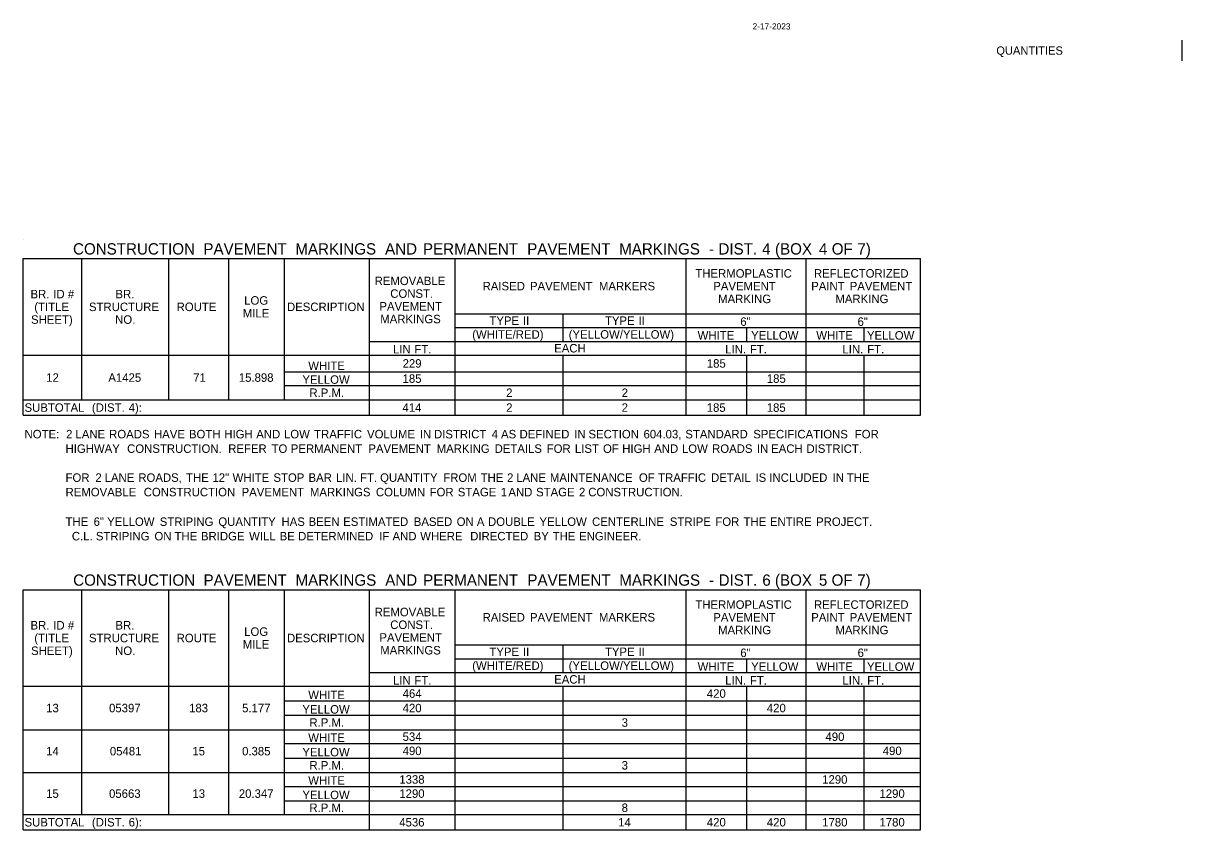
# Model space of a CAD drawing. Extents: x 544255 to 1930787, y -1947044 to 596640.
# Drawn here: x 544975 to 545794, y -1946596 to -1946026 of the extents above; entities that cross this region are included whole.
import ezdxf

# ---------------------------------------------------------------- set-up
doc = ezdxf.new("R2010")
doc.units = 0
doc.layers.add('Default', color=7, linetype='Continuous')
doc.layers.add('R_Border Prem', color=7, linetype='Continuous')

msp = doc.modelspace()

# ---------------------------------------------------------------- linework, layer by layer
at = {"layer": 'Default'}
for p, q in [((545794.28, -1946038.1), (545794.28, -1946052.8)), ((544975.46, -1946178.75), (544975.46, -1946178.75)), ((544975.46, -1946192.4), (545609.7, -1946192.4)), ((544975.46, -1946192.4), (545280.64, -1946192.4)), ((544975.46, -1946303.06), (544975.46, -1946192.4)), ((545016.9, -1946292.34), (545016.9, -1946192.4)), ((545078.33, -1946292.34), (545078.33, -1946192.4)), ((545120.74, -1946292.34), (545120.74, -1946192.4)), ((545160.23, -1946292.34), (545160.23, -1946192.4)), ((545220.19, -1946303.06), (545220.19, -1946192.4)), ((545280.64, -1946303.06), (545280.64, -1946192.4)), ((545443.95, -1946303.06), (545443.95, -1946192.4)), ((545528.78, -1946260.65), (545528.78, -1946192.4)), ((545528.78, -1946303.06), (545528.78, -1946192.4)), ((545609.7, -1946303.06), (545609.7, -1946192.4)), ((545280.64, -1946231.4), (545609.7, -1946231.4)), ((545357.18, -1946250.9), (545357.18, -1946231.4)), ((545280.64, -1946241.15), (545609.7, -1946241.15)), ((545486.85, -1946250.9), (545486.85, -1946241.15)), ((545569.73, -1946250.9), (545569.73, -1946241.15)), ((545220.19, -1946250.9), (545609.7, -1946250.9)), ((545220.19, -1946260.65), (545220.19, -1946250.9)), ((544975.46, -1946260.65), (545160.23, -1946260.65)), ((544975.46, -1946260.65), (545120.74, -1946260.65)), ((545120.74, -1946260.65), (545609.7, -1946260.65)), ((545357.18, -1946303.06), (545357.18, -1946260.65)), ((545443.95, -1946260.65), (545528.78, -1946260.65)), ((545486.85, -1946303.06), (545486.85, -1946260.65)), ((545528.78, -1946260.65), (545609.7, -1946260.65)), ((545569.73, -1946303.06), (545569.73, -1946260.65)), ((545160.23, -1946272.35), (545609.7, -1946272.35)), ((545160.23, -1946282.1), (545609.7, -1946282.1)), ((544975.46, -1946292.34), (545609.7, -1946292.34)), ((545220.19, -1946303.06), (545220.19, -1946292.34)), ((544975.46, -1946303.06), (545609.7, -1946303.06)), ((544975.46, -1946426.4), (545609.7, -1946426.4)), ((544975.46, -1946426.4), (545280.64, -1946426.4)), ((544975.46, -1946596.05), (544975.46, -1946426.4)), ((545016.9, -1946585.32), (545016.9, -1946426.4)), ((545078.33, -1946585.32), (545078.33, -1946426.4)), ((545120.74, -1946585.32), (545120.74, -1946426.4)), ((545160.23, -1946585.32), (545160.23, -1946426.4)), ((545220.19, -1946596.05), (545220.19, -1946426.4)), ((545280.64, -1946596.05), (545280.64, -1946426.4)), ((545443.95, -1946596.05), (545443.95, -1946426.4)), ((545528.78, -1946494.65), (545528.78, -1946426.4)), ((545528.78, -1946596.05), (545528.78, -1946426.4)), ((545609.7, -1946596.05), (545609.7, -1946426.4)), ((545280.64, -1946465.4), (545609.7, -1946465.4)), ((545357.18, -1946484.9), (545357.18, -1946465.4)), ((545280.64, -1946475.15), (545609.7, -1946475.15)), ((545486.85, -1946484.9), (545486.85, -1946475.15)), ((545569.73, -1946484.9), (545569.73, -1946475.15)), ((545220.19, -1946484.9), (545609.7, -1946484.9)), ((545220.19, -1946494.65), (545220.19, -1946484.9)), ((544975.46, -1946494.65), (545160.23, -1946494.65)), ((544975.46, -1946494.65), (545120.74, -1946494.65)), ((545120.74, -1946494.65), (545609.7, -1946494.65)), ((545357.18, -1946596.05), (545357.18, -1946494.65)), ((545443.95, -1946494.65), (545528.78, -1946494.65)), ((545486.85, -1946596.05), (545486.85, -1946494.65)), ((545528.78, -1946494.65), (545609.7, -1946494.65)), ((545569.73, -1946596.05), (545569.73, -1946494.65)), ((545160.23, -1946504.89), (545609.7, -1946504.89)), ((545160.23, -1946515.12), (545609.7, -1946515.12)), ((544975.46, -1946525.36), (545609.7, -1946525.36)), ((545160.23, -1946535.11), (545609.7, -1946535.11)), ((545160.23, -1946545.35), (545609.7, -1946545.35)), ((544975.46, -1946555.59), (545609.7, -1946555.59)), ((545160.23, -1946565.34), (545609.7, -1946565.34)), ((545160.23, -1946575.57), (545609.7, -1946575.57)), ((544975.46, -1946585.32), (545609.7, -1946585.32)), ((545220.19, -1946596.05), (545220.19, -1946585.32)), ((544975.46, -1946596.05), (545609.7, -1946596.05))]:
    msp.add_line(p, q, dxfattribs=at)

# ---------------------------------------------------------------- texts
for s, height, p in [('CONSTRUCTION', 8, (545010.7, -1946189.57)), (' PAVEMENT', 8, (545099.85, -1946189.57)), (' MARKINGS', 8, (545164.84, -1946189.57)), (' AND', 8, (545228.25, -1946189.57)), (' PERMANENT', 8, (545255.02, -1946189.57)), (' PAVEMENT', 8, (545328.7, -1946189.57)), (' MARKINGS', 8, (545393.68, -1946189.57)), (' -', 8, (545457.1, -1946189.57)), (' DIST.', 8, (545463.84, -1946189.57)), (' 4', 8, (545494.74, -1946189.57)), (' (BOX', 8, (545503.81, -1946189.57)), (' 4', 8, (545534.84, -1946189.57)), (' OF', 8, (545543.9, -1946189.57)), (' 7)', 8, (545562.01, -1946189.57)), ('THERMOPLASTIC', 6, (545450.48, -1946205.9)), ('REFLECTORIZED', 6, (545534.28, -1946205.9)), ('REMOVABLE', 6, (545223.84, -1946211.15)), ('RAISED', 6, (545300.14, -1946214.9)), (' PAVEMENT', 6, (545331.4, -1946214.9)), (' MARKERS', 6, (545380.14, -1946214.9)), ('PAVEMENT', 6, (545463.16, -1946214.9)), ('PAINT', 6, (545532.38, -1946214.9)), (' PAVEMENT', 6, (545557.36, -1946214.9)), ('BR.', 6, (544980.66, -1946220.52)), (' ID', 6, (544994.52, -1946220.52)), (' #', 6, (545004.81, -1946220.52)), ('BR.', 6, (545040.68, -1946220.52)), ('LOG', 6, (545131.65, -1946225.02)), ('CONST.', 6, (545234.87, -1946220.15)), ('MARKING', 6, (545466.59, -1946223.9)), ('MARKING', 6, (545549.47, -1946223.9)), ('(TITLE', 6, (544983.35, -1946229.52)), ('STRUCTURE', 6, (545021.97, -1946229.52)), ('ROUTE', 6, (545083.9, -1946229.52)), ('MILE', 6, (545130.68, -1946234.02)), ('DESCRIPTION', 6, (545161.9, -1946229.52)), ('PAVEMENT', 6, (545227.21, -1946229.15)), ('SHEET)', 6, (544981.03, -1946238.52)), ('NO.', 6, (545040.45, -1946238.52)), ('MARKINGS', 6, (545227.8, -1946238.15)), ('TYPE', 6, (545304.95, -1946239.27)), (' II', 6, (545326.43, -1946239.27)), ('TYPE', 6, (545386.6, -1946239.27)), (' II', 6, (545408.09, -1946239.27)), ('6"', 6, (545482.26, -1946239.95)), ('6"', 6, (545565.13, -1946239.95)), ('(WHITE/RED)', 6, (545292.82, -1946249.02)), ('(YELLOW/YELLOW)', 6, (545360.97, -1946249.02)), ('WHITE', 6, (545452.11, -1946249.7)), ('YELLOW', 6, (545489.89, -1946249.7)), ('WHITE', 6, (545535.96, -1946249.7)), ('YELLOW', 6, (545571.79, -1946249.7)), ('EACH', 6, (545350.74, -1946258.77)), ('LIN', 6, (545236.84, -1946259.45)), (' FT.', 6, (545249.67, -1946259.45)), ('LIN.', 6, (545471.57, -1946259.45)), (' FT.', 6, (545486.83, -1946259.45)), ('LIN.', 6, (545554.45, -1946259.45)), (' FT.', 6, (545569.71, -1946259.45)), ('WHITE', 6, (545176.93, -1946271.15)), ('229', 6, (545243.61, -1946269.5)), ('185', 6, (545458.58, -1946269.5)), ('12', 6, (544991.74, -1946279.49)), ('A1425', 6, (545035.66, -1946279.49)), ('71', 6, (545095.64, -1946279.49)), ('15.898', 6, (545127.85, -1946279.49)), ('YELLOW', 6, (545172.79, -1946280.9)), ('185', 6, (545243.59, -1946280.22)), ('185', 6, (545500.99, -1946280.22)), ('R.P.M.', 6, (545177.77, -1946290.22)), ('2', 6, (545316.8, -1946290.22)), ('2', 6, (545398.46, -1946290.22)), ('SUBTOTAL', 6, (544976.44, -1946300.7)), (' (DIST.', 6, (545021.83, -1946300.7)), (' 4):', 6, (545047.8, -1946300.7)), ('414', 6, (545243.52, -1946300.7)), ('2', 6, (545316.79, -1946300.7)), ('2', 6, (545398.44, -1946300.7)), ('185', 6, (545458.54, -1946300.7)), ('185', 6, (545500.95, -1946300.7)), ('NOTE:', 6, (544976.44, -1946319.47)), ('  2', 6, (545001.33, -1946319.47)), (' LANE', 6, (545010.2, -1946319.47)), (' ROADS', 6, (545033.98, -1946319.47)), (' HAVE', 6, (545065.68, -1946319.47)), (' BOTH', 6, (545090.4, -1946319.47)), (' HIGH', 6, (545115.34, -1946319.47)), (' AND', 6, (545137.95, -1946319.47)), (' LOW', 6, (545157.53, -1946319.47)), (' TRAFFIC', 6, (545178.86, -1946319.47)), (' VOLUME', 6, (545216.25, -1946319.47)), (' IN', 6, (545253.53, -1946319.47)), (' DISTRICT', 6, (545263.56, -1946319.47)), (' 4', 6, (545304.37, -1946319.47)), (' AS', 6, (545310.95, -1946319.47)), (' DEFINED', 6, (545324.03, -1946319.47)), (' IN', 6, (545362.71, -1946319.47)), (' SECTION', 6, (545372.73, -1946319.47)), (' 604.03,', 6, (545411.64, -1946319.47)), (' STANDARD', 6, (545441.18, -1946319.47)), (' SPECIFICATIONS', 6, (545489.18, -1946319.47)), (' FOR', 6, (545560.95, -1946319.47)), ('             HIGHWAY', 6, (544976.44, -1946329.7)), (' CONSTRUCTION.', 6, (545046.69, -1946329.7)), (' REFER', 6, (545118.15, -1946329.7)), (' TO', 6, (545148.78, -1946329.7)), (' PERMANENT', 6, (545162.38, -1946329.7)), (' PAVEMENT', 6, (545217.18, -1946329.7)), (' MARKING', 6, (545265.46, -1946329.7)), (' DETAILS', 6, (545306.39, -1946329.7)), (' FOR', 6, (545343.23, -1946329.7)), (' LIST', 6, (545363.14, -1946329.7)), (' OF', 6, (545383, -1946329.7)), (' HIGH', 6, (545396.59, -1946329.7)), (' AND', 6, (545419.2, -1946329.7)), (' LOW', 6, (545438.78, -1946329.7)), (' ROADS', 6, (545460.1, -1946329.7)), (' IN', 6, (545491.81, -1946329.7)), (' EACH', 6, (545501.83, -1946329.7)), (' DISTRICT.', 6, (545526.78, -1946329.7)), ('             FOR', 6, (544976.44, -1946350.18)), (' 2', 6, (545024.28, -1946350.18)), (' LANE', 6, (545030.83, -1946350.18)), (' ROADS,', 6, (545054.61, -1946350.18)), (' THE', 6, (545088.34, -1946350.18)), (' 12"', 6, (545106.98, -1946350.18)), (' WHITE', 6, (545121.22, -1946350.18)), (' STOP', 6, (545150.11, -1946350.18)), (' BAR', 6, (545174.9, -1946350.18)), (' LIN.', 6, (545194.35, -1946350.18)), (' FT.', 6, (545211.32, -1946350.18)), (' QUANTITY', 6, (545225.48, -1946350.18)), (' FROM', 6, (545270.14, -1946350.18)), (' THE', 6, (545296.52, -1946350.18)), (' 2', 6, (545315.16, -1946350.18)), (' LANE', 6, (545321.71, -1946350.18)), (' MAINTENANCE', 6, (545345.49, -1946350.18)), (' OF', 6, (545408.39, -1946350.18)), (' TRAFFIC', 6, (545421.98, -1946350.18)), (' DETAIL', 6, (545459.37, -1946350.18)), (' IS', 6, (545490.75, -1946350.18)), (' INCLUDED', 6, (545500.56, -1946350.18)), (' IN', 6, (545545.3, -1946350.18)), (' THE', 6, (545555.32, -1946350.18)), ('             REMOVABLE', 6, (544976.44, -1946360.42)), (' CONSTRUCTION', 6, (545058.44, -1946360.42)), (' PAVEMENT', 6, (545127.61, -1946360.42)), (' MARKINGS', 6, (545175.9, -1946360.42)), (' COLUMN', 6, (545222.51, -1946360.42)), (' FOR', 6, (545260.48, -1946360.42)), (' STAGE', 6, (545280.39, -1946360.42)), (' 1', 6, (545310.69, -1946360.42)), (' AND', 6, (545316.14, -1946360.42)), (' STAGE', 6, (545335.72, -1946360.42)), (' 2', 6, (545366.02, -1946360.42)), (' CONSTRUCTION.', 6, (545372.57, -1946360.42)), ('             THE', 6, (544976.44, -1946381.32)), (' 6"', 6, (545023.02, -1946381.32)), (' YELLOW', 6, (545032.59, -1946381.32)), (' STRIPING', 6, (545069.76, -1946381.32)), (' QUANTITY', 6, (545111.16, -1946381.32)), (' HAS', 6, (545155.81, -1946381.32)), (' BEEN', 6, (545174.94, -1946381.32)), (' ESTIMATED', 6, (545199.42, -1946381.32)), (' BASED', 6, (545249.28, -1946381.32)), (' ON', 6, (545279.59, -1946381.32)), (' A', 6, (545293.8, -1946381.32)), (' DOUBLE', 6, (545301.74, -1946381.32)), (' YELLOW', 6, (545338.09, -1946381.32)), (' CENTERLINE', 6, (545375.27, -1946381.32)), (' STRIPE', 6, (545430.25, -1946381.32)), (' FOR', 6, (545462.42, -1946381.32)), (' THE', 6, (545482.33, -1946381.32)), (' ENTIRE', 6, (545500.98, -1946381.32)), (' PROJECT.', 6, (545533.6, -1946381.32)), (' C.L.', 6, (545007.64, -1946391.56)), (' STRIPING', 6, (545024.61, -1946391.56)), (' ON', 6, (545066, -1946391.56)), (' THE', 6, (545080.22, -1946391.56)), (' BRIDGE', 6, (545098.87, -1946391.56)), (' WILL', 6, (545132.89, -1946391.56)), (' BE', 6, (545154.48, -1946391.56)), (' DETERMINED', 6, (545167.55, -1946391.56)), (' IF', 6, (545224.86, -1946391.56)), (' AND', 6, (545234.25, -1946391.56)), (' WHERE', 6, (545253.84, -1946391.56)), ('  DIRECTED', 6, (545286.92, -1946391.56)), (' BY', 6, (545333.99, -1946391.56)), (' THE', 6, (545347.43, -1946391.56)), (' ENGINEER.', 6, (545366.08, -1946391.56)), ('CONSTRUCTION', 8, (545010.81, -1946423.57)), (' PAVEMENT', 8, (545099.96, -1946423.57)), (' MARKINGS', 8, (545164.95, -1946423.57)), (' AND', 8, (545228.36, -1946423.57)), (' PERMANENT', 8, (545255.13, -1946423.57)), (' PAVEMENT', 8, (545328.81, -1946423.57)), (' MARKINGS', 8, (545393.79, -1946423.57)), (' DIST.', 8, (545463.95, -1946423.57)), (' 6', 8, (545494.85, -1946423.57)), (' (BOX', 8, (545503.77, -1946423.57)), (' 5', 8, (545534.81, -1946423.57)), (' OF', 8, (545543.79, -1946423.57)), (' 7)', 8, (545561.9, -1946423.57)), (' -', 8, (545457.21, -1946423.57)), ('REMOVABLE', 6, (545223.84, -1946445.15)), ('THERMOPLASTIC', 6, (545450.48, -1946439.9)), ('REFLECTORIZED', 6, (545534.28, -1946439.9)), ('BR.', 6, (544980.66, -1946454.52)), (' ID', 6, (544994.52, -1946454.52)), (' #', 6, (545004.81, -1946454.52)), ('BR.', 6, (545040.68, -1946454.52)), ('CONST.', 6, (545234.87, -1946454.15)), ('RAISED', 6, (545300.14, -1946448.9)), (' PAVEMENT', 6, (545331.4, -1946448.9)), (' MARKERS', 6, (545380.14, -1946448.9)), ('PAVEMENT', 6, (545463.16, -1946448.9)), ('PAINT', 6, (545532.38, -1946448.9)), (' PAVEMENT', 6, (545557.36, -1946448.9)), ('(TITLE', 6, (544983.35, -1946463.52)), ('STRUCTURE', 6, (545021.97, -1946463.52)), ('ROUTE', 6, (545083.9, -1946463.52)), ('LOG', 6, (545131.65, -1946459.02)), ('DESCRIPTION', 6, (545161.9, -1946463.52)), ('PAVEMENT', 6, (545227.21, -1946463.15)), ('MARKING', 6, (545466.59, -1946457.9)), ('MARKING', 6, (545549.47, -1946457.9)), ('SHEET)', 6, (544981.03, -1946472.52)), ('MILE', 6, (545130.68, -1946468.02)), ('MARKINGS', 6, (545227.8, -1946472.15)), ('NO.', 6, (545040.45, -1946472.52)), ('TYPE', 6, (545304.95, -1946473.27)), (' II', 6, (545326.43, -1946473.27)), ('TYPE', 6, (545386.6, -1946473.27)), (' II', 6, (545408.09, -1946473.27)), ('6"', 6, (545482.26, -1946473.95)), ('6"', 6, (545565.13, -1946473.95)), ('(WHITE/RED)', 6, (545292.82, -1946483.02)), ('(YELLOW/YELLOW)', 6, (545360.97, -1946483.02)), ('WHITE', 6, (545452.11, -1946483.7)), ('YELLOW', 6, (545489.89, -1946483.7)), ('WHITE', 6, (545535.96, -1946483.7)), ('YELLOW', 6, (545571.79, -1946483.7)), ('LIN', 6, (545236.84, -1946493.45)), (' FT.', 6, (545249.67, -1946493.45)), ('EACH', 6, (545350.74, -1946492.77)), ('LIN.', 6, (545471.57, -1946493.45)), (' FT.', 6, (545486.83, -1946493.45)), ('LIN.', 6, (545554.45, -1946493.45)), (' FT.', 6, (545569.71, -1946493.45)), ('WHITE', 6, (545176.93, -1946503.69)), ('464', 6, (545243.63, -1946502.77)), ('420', 6, (545458.61, -1946502.77)), ('13', 6, (544991.71, -1946513)), ('05397', 6, (545036.15, -1946513)), ('183', 6, (545092.73, -1946513)), ('5.177', 6, (545130.19, -1946513)), ('420', 6, (545243.63, -1946513)), ('420', 6, (545501.03, -1946513)), ('YELLOW', 6, (545172.79, -1946513.92)), ('R.P.M.', 6, (545177.77, -1946523.24)), ('3', 6, (545398.42, -1946523.24)), ('WHITE', 6, (545176.93, -1946533.91)), ('534', 6, (545243.63, -1946533.24)), ('490', 6, (545542.46, -1946533.24)), ('14', 6, (544991.73, -1946543.47)), ('05481', 6, (545036.73, -1946543.47)), ('15', 6, (545095.04, -1946543.47)), ('0.385', 6, (545130.17, -1946543.47)), ('YELLOW', 6, (545172.79, -1946544.15)), ('490', 6, (545243.63, -1946543.23)), ('490', 6, (545582.93, -1946543.23)), ('R.P.M.', 6, (545177.77, -1946553.47)), ('3', 6, (545398.42, -1946553.47)), ('WHITE', 6, (545176.93, -1946564.14)), ('1338', 6, (545241.28, -1946563.46)), ('1290', 6, (545540.13, -1946563.46)), ('15', 6, (544991.69, -1946573.45)), ('05663', 6, (545036.15, -1946573.45)), ('13', 6, (545095.06, -1946573.45)), ('20.347', 6, (545127.86, -1946573.45)), ('YELLOW', 6, (545172.79, -1946574.37)), ('1290', 6, (545241.3, -1946573.45)), ('1290', 6, (545580.6, -1946573.45)), ('R.P.M.', 6, (545177.77, -1946583.45)), ('8', 6, (545398.42, -1946583.45)), ('SUBTOTAL', 6, (544976.44, -1946593.69)), (' (DIST.', 6, (545021.83, -1946593.69)), (' 6):', 6, (545047.8, -1946593.69)), ('4536', 6, (545241.24, -1946593.69)), ('14', 6, (545396, -1946593.69)), ('420', 6, (545458.62, -1946593.69)), ('420', 6, (545501.03, -1946593.69)), ('1780', 6, (545540.14, -1946593.69)), ('1780', 6, (545580.6, -1946593.69))]:
    msp.add_text(s, height=height, dxfattribs=at).set_placement(p)
at = {"layer": 'R_Border Prem'}
msp.add_text('2-17-2023', height=4.396, dxfattribs=at).set_placement((545490.92, -1946030.56))
msp.add_text('QUANTITIES', height=5.862, rotation=360, dxfattribs=at).set_placement((545663.18, -1946048.38))

doc.saveas('drawing.dxf')
